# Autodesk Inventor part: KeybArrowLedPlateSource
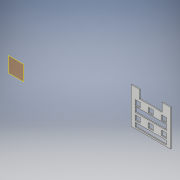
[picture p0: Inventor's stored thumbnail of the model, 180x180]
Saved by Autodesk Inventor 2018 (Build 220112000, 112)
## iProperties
Created: 2017-10
Part Number: KeybArrowLedPlateSource
Material: Generic
Document SubType Name: Modeling
Designer: Buddy
Density: 1 g/cm^3
Appearance: Default
Author: Buddy
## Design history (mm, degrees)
sketch "File Was"
  geometry: L1 (222.827, 62.893)-(216.827, 62.893); L2 (222.827, 62.893)-(222.827, 10.794); L3 (222.827, 10.794)-(165.677, 10.794); L4 (165.677, 10.794)-(165.677, 62.893); L5 (165.677, 62.893)-(171.677, 62.893); L6 (165.677, 62.893)-(171.677, 62.893); L7 (216.827, 62.893)-(222.827, 62.893); L8 (222.827, 62.893)-(222.827, 10.794); L9 (222.827, 10.794)-(165.677, 10.794); L10 (165.677, 10.794)-(165.677, 62.893); L11 (171.677, 62.893)-(177.773, 62.893); L12 (177.773, 62.893)-(177.773, 50.758); L13 (216.827, 62.893)-(210.731, 62.893); L14 (210.731, 62.893)-(210.731, 50.758); L15 (210.731, 50.758)-(177.773, 50.758); L16 (171.701, 47.213)-(178.701, 47.213); L17 (178.701, 47.213)-(178.701, 40.213); L18 (178.701, 40.213)-(171.701, 40.213); L19 (171.701, 40.213)-(171.701, 47.213); L20 (171.701, 47.213)-(178.701, 40.213); L21 (178.701, 47.213)-(171.701, 40.213); L22 (190.751, 47.213)-(197.751, 47.213); L23 (197.751, 47.213)-(197.751, 40.213); L24 (197.751, 40.213)-(190.751, 40.213); L25 (190.751, 40.213)-(190.751, 47.213); L26 (190.751, 47.213)-(197.751, 40.213); L27 (197.751, 47.213)-(190.751, 40.213); L28 (209.801, 47.213)-(216.801, 47.213); L29 (216.801, 47.213)-(216.801, 40.213); L30 (216.801, 40.213)-(209.801, 40.213); L31 (209.801, 40.213)-(209.801, 47.213); L32 (209.801, 47.213)-(216.801, 40.213); L33 (216.801, 47.213)-(209.801, 40.213); L34 (171.701, 28.163)-(178.701, 28.163); L35 (178.701, 28.163)-(178.701, 21.163); L36 (178.701, 21.163)-(171.701, 21.163); L37 (171.701, 21.163)-(171.701, 28.163); L38 (171.701, 28.163)-(178.701, 21.163); L39 (178.701, 28.163)-(171.701, 21.163); L40 (190.751, 28.163)-(197.751, 28.163); L41 (197.751, 28.163)-(197.751, 21.163); L42 (197.751, 21.163)-(190.751, 21.163); L43 (190.751, 21.163)-(190.751, 28.163); L44 (190.751, 28.163)-(197.751, 21.163); L45 (197.751, 28.163)-(190.751, 21.163); L46 (209.801, 28.163)-(216.801, 28.163); L47 (216.801, 28.163)-(216.801, 21.163); L48 (216.801, 21.163)-(209.801, 21.163); L49 (209.801, 21.163)-(209.801, 28.163); L50 (209.801, 28.163)-(216.801, 21.163); L51 (216.801, 28.163)-(209.801, 21.163); 1 further point
  constraints: 102 end point, 15 equal length, 10 perpendicular, 8 horizontal
  dimensions: "d5" = 6.096 distance of L6.end L11.end; "d6" = 6.096 distance of L1.end L13.end; "d15" = 7 distance of L16.end L17.end; "d17" = 7 distance of L22.end L23.end; "d19" = 7 distance of L28.end L29.end; "d21" = 7 distance of L34.end L35.end; "d23" = 7 distance of L40.end L41.end; "d25" = 7 distance of L46.end L47.end
node "Designed By"
node "Foster Phillips (Lego_Rocket_08 on Instagram)"
extrude "https://www.fiverr.com/lego_rocket (For Commisions)" new body sketch "File Was" distance "d26" = 1.3; taper "d27" = 0 deg
sketch "Thanks!"
  geometry: L1 (171.753, 38.87)-(216.913, 38.87); L2 (216.913, 38.87)-(216.913, 31.274); L3 (216.913, 31.274)-(171.753, 31.274); L4 (171.753, 31.274)-(171.753, 38.87); L5 (171.753, 18.961)-(216.913, 18.961); L6 (216.913, 18.961)-(216.913, 12.953); L7 (216.913, 12.953)-(171.753, 12.953); L8 (171.753, 12.953)-(171.753, 18.961); 1 further point
  constraints: 16 end point, 4 parallel, 2 horizontal, 2 perpendicular, 1 point on line
extrude "Posted by: https://www.instructables.com/member/FosterP/" cut sketch "Thanks!" distance "d28" = 25.4; taper "d29" = 0 deg
body "Solid2"
